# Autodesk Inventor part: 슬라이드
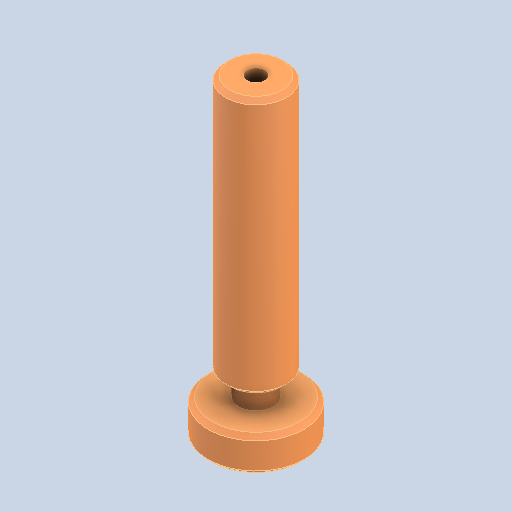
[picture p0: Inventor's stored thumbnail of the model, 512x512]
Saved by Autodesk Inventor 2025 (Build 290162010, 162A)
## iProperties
Created: 2024-07
Part Number: 슬라이드
Material: 강철, 연강
Document SubType Name: Modeling
Designer: 학생
Density: 7.86 g/cm^3
Appearance: 기본값
Author: jhkim
Sending System: Autodesk Inventor 2025
Preprocessor: ST-DEVELOPER v20
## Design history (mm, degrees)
feature "솔리드1"
node "솔리드2"
